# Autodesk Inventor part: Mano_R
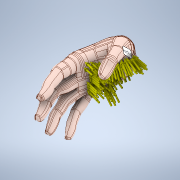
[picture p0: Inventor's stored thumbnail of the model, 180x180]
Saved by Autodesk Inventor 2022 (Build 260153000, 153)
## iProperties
Created: 2022-05
Part Number: Mano_R
Material: Generic
Document SubType Name: Modeling
Designer: Administrator
Density: 1 g/cm^3
Appearance: Default
Title: Mano_R v1
Author: Administrator
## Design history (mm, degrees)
feature "Mano_mano"
body "Solid1"
other parameters: "sa_0" = 2224110.80763, "sa_1" = 344737.86466, "sa_2" = 2224110.80763, "sa_3" = 2224110.80763, "sa_4" = 689475.72932
